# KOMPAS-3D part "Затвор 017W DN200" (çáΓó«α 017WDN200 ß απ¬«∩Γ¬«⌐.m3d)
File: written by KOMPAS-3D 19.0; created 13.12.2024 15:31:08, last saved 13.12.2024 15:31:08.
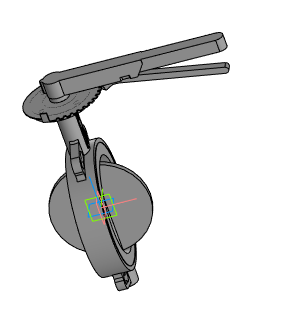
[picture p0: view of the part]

Document properties: Автор: Евгений; Полное имя файла: ..\Затвор 017WDN200.a3d

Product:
- Part/product: Затвор 017W DN200
    Масса: 22.7045

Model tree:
1. Операция без истории:1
